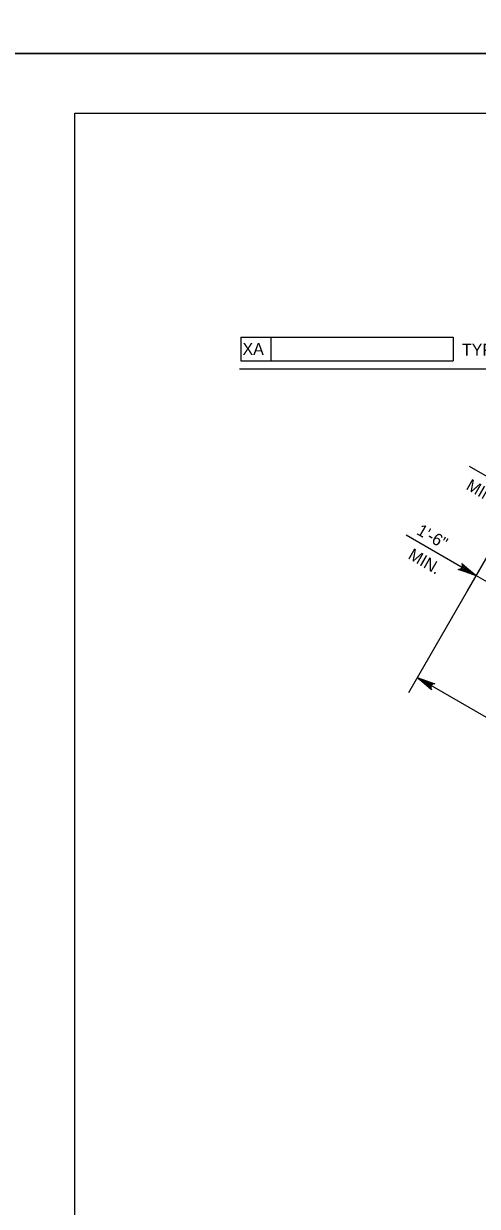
# Model space of a CAD drawing. Extents: x 638340 to 640242, y 295465 to 298435.
# Drawn here: x 639303.6 to 639417.6, y 296364 to 296661 of the extents above; entities that cross this region are included whole.
import ezdxf

# ---------------------------------------------------------------- set-up
doc = ezdxf.new("R2010")
doc.units = 0
for name, color, linetype in [('2', 7, 'Continuous'), ('Level 2', 7, 'Continuous'), ('PLT-BNDY', 7, 'Continuous')]:
    doc.layers.add(name, color=color, linetype=linetype)

msp = doc.modelspace()

# ---------------------------------------------------------------- linework, layer by layer
at = {"layer": '2'}
for p, q in [((639316.46, 296074.46), (639316.46, 296638.46)), ((639316.46, 296638.46), (640102.69, 296638.46))]:
    msp.add_line(p, q, dxfattribs=at)
at = {"layer": 'Level 2'}
for p, q in [((639358.15, 296582.21), (639411.53, 296582.21)), ((639358.15, 296582.21), (639358.15, 296576.32)), ((639365.7, 296582.21), (639365.7, 296576.32)), ((639411.53, 296582.21), (639411.53, 296576.32)), ((639358.15, 296576.32), (639411.53, 296576.32)), ((639433.77, 296550.86), (639400.31, 296492.92)), ((639433.77, 296550.86), (639415.09, 296518.51)), ((639428.75, 296542.18), (639415.69, 296549.71)), ((639417.3, 296522.34), (639399.74, 296532.48)), ((639423.68, 296518.66), (639417.3, 296522.34)), ((639478.34, 296452.97), (639402.52, 296496.75))]:
    msp.add_line(p, q, dxfattribs=at)
for points in [[(639444.6, 296554.89), (639424.29, 296574.17), (639357.84, 296574.17)], [(639417.3, 296522.34), (639412.84, 296523.91), (639413.27, 296523.95), (639413.59, 296524.13), (639413.79, 296524.37), (639413.9, 296524.67), (639413.89, 296525.03), (639413.71, 296525.42), (639417.3, 296522.34), (639413.89, 296525.03), (639413.9, 296524.67), (639417.3, 296522.34), (639413.79, 296524.37), (639413.59, 296524.13), (639417.3, 296522.34), (639413.27, 296523.95)], [(639402.52, 296496.75), (639406.99, 296495.18), (639406.55, 296495.14), (639406.24, 296494.96), (639406.03, 296494.72), (639405.92, 296494.42), (639405.93, 296494.06), (639406.12, 296493.66), (639402.52, 296496.75), (639405.93, 296494.06), (639405.92, 296494.42), (639402.52, 296496.75), (639406.03, 296494.72), (639406.24, 296494.96), (639402.52, 296496.75), (639406.55, 296495.14)]]:
    msp.add_lwpolyline(points, dxfattribs=at)
for points in [[(639414.99, 296524.24), (639414.5, 296523.39), (639417.3, 296522.34)], [(639405.32, 296495.7), (639404.83, 296494.84), (639402.52, 296496.75)]]:
    msp.add_lwpolyline(points, close=True, dxfattribs=at)
at = {"layer": 'PLT-BNDY'}
for points in [[(639276.46, 297247.46), (640117.46, 297247.46), (640117.46, 296653.46), (639276.46, 296653.46)], [(639276.46, 296653.46), (640117.46, 296653.46), (640117.46, 296059.46), (639276.46, 296059.46)]]:
    msp.add_lwpolyline(points, close=True, dxfattribs=at)

# ---------------------------------------------------------------- texts
at = {"layer": 'Level 2'}
for s, rotation, p in [('XA', 359.9382, (639358.61, 296577.77)), ('MIN.', 330, (639414.58, 296544.17)), ('1\'-6"', 330, (639402.14, 296532.87)), ('MIN.', 330, (639400, 296526.76))]:
    msp.add_text(s, height=3, rotation=rotation, dxfattribs=at).set_placement(p)
msp.add_text('TYP.', height=3, dxfattribs=at).set_placement((639413.78, 296577.61))

doc.saveas('drawing.dxf')
